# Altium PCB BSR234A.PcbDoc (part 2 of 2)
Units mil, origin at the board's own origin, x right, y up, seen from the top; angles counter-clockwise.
Board outline 3000 x 2500 mil, 4 copper layers (Top Layer, Signal Layer 1, Signal Layer 2, Bottom Layer), stack 61.2 mil thick; 82 components, 24 nets, 148 pads, 419 vias.
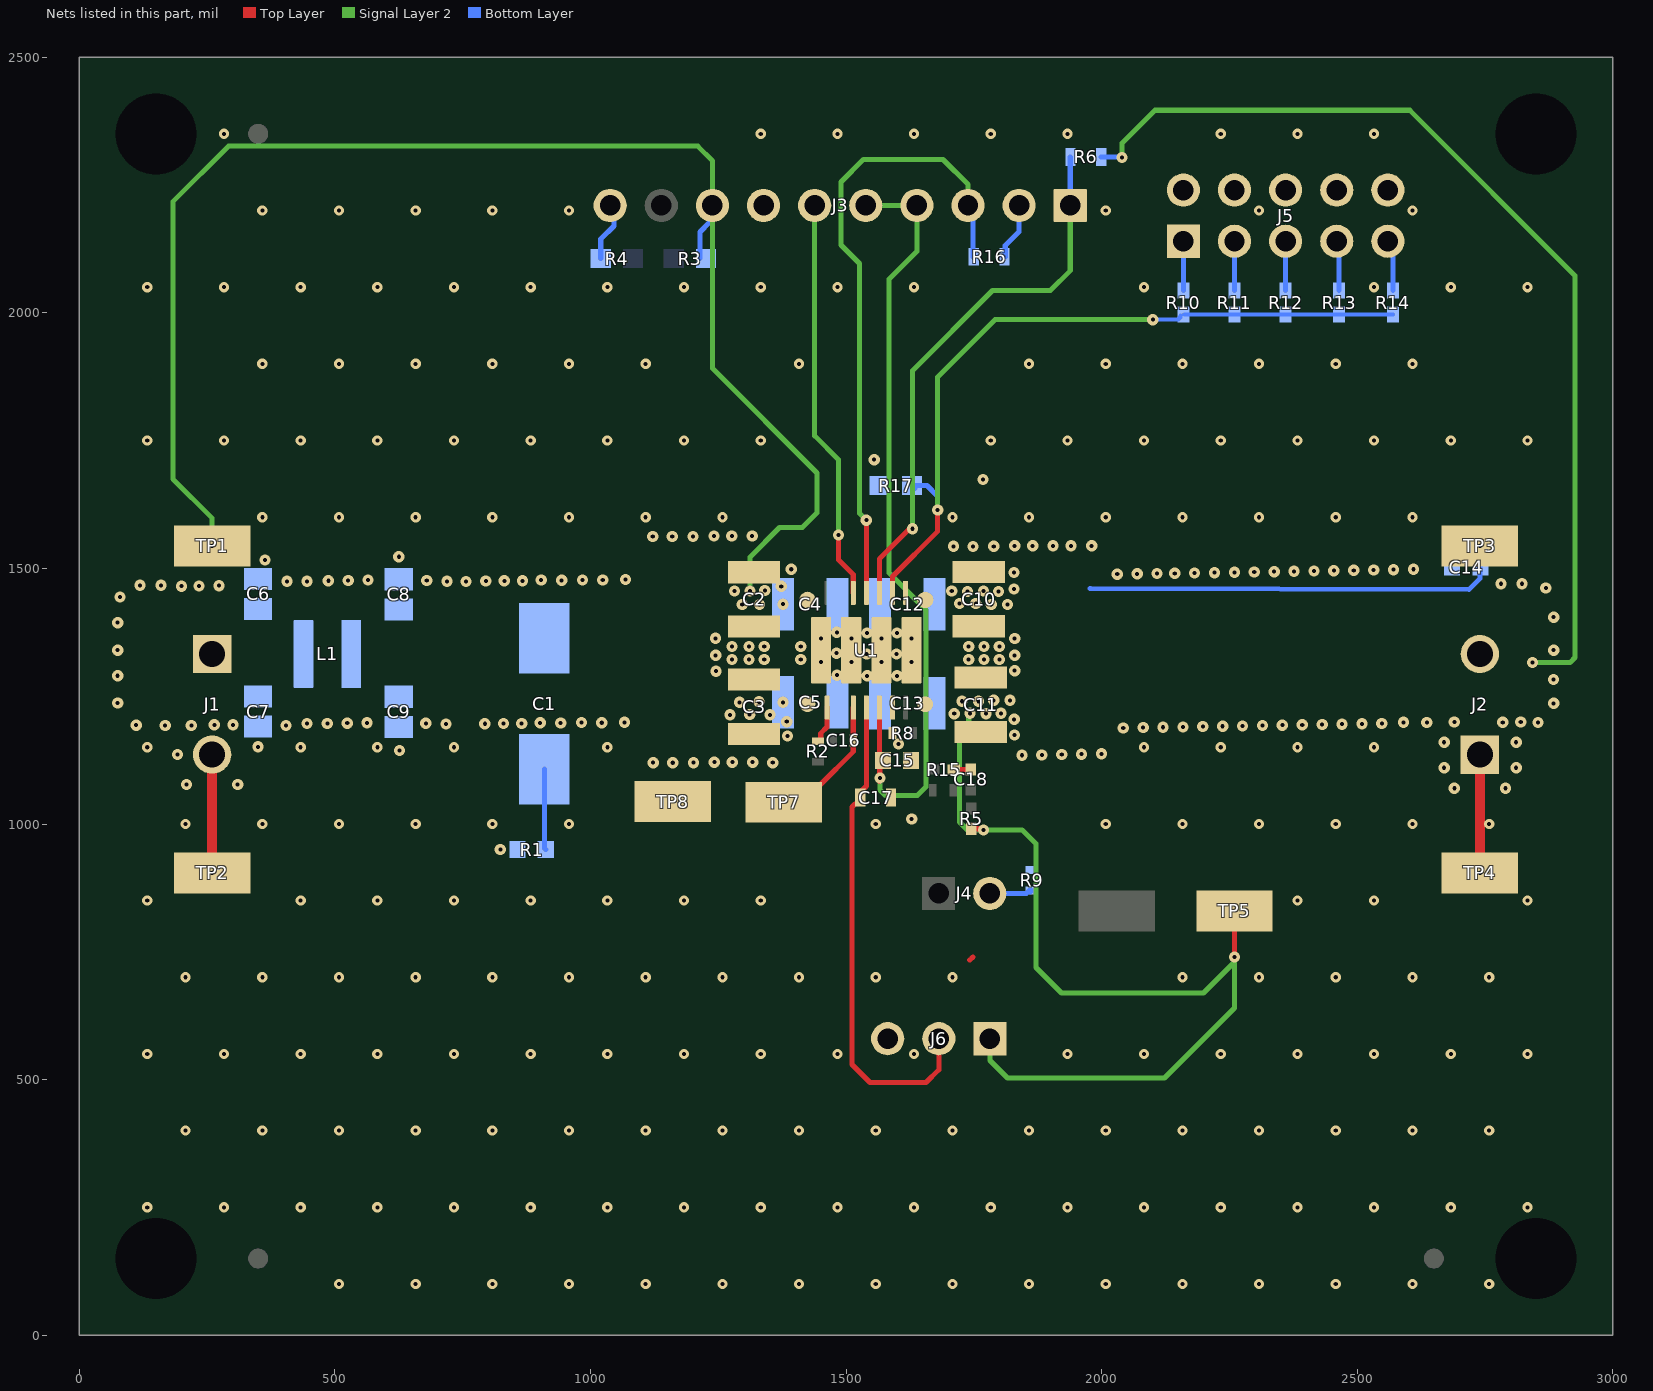
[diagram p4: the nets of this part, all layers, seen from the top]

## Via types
v1: diameter 22, hole 8, Top Layer to Bottom Layer, tented both sides, 213 vias
v2: diameter 20, hole 8, Top Layer to Bottom Layer, tented both sides, 196 vias
v3: diameter 19.68, hole 7.87, Top Layer to Bottom Layer, tented both sides, 8 vias
v4: diameter 22, hole 8, Top Layer to Bottom Layer, 2 vias

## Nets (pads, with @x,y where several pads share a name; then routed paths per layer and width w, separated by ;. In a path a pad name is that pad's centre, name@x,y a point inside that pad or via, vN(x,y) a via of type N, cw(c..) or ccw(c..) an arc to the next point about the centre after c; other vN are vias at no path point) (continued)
GND: C2.1 C3.1 C4.1 C5.1 C6.2 C7.2 C8.2 C9.2 C10.1 C11.1 C12.2 C13.2 C14.2 C15.2 C17.1 J1.2 J2.1 J3.2 J3.7 J3.10 J5.2 J5.4 J5.6 J5.8 J5.10 J6.3 R1.1 R4.1 R8.1 R9.1 R16.1 R17.1 TP2.1 TP4.1 TP8.1 U1.7 U1.11 U1.19 U1.20 U1.21 U1.22 | length 704.4
  Top Layer w10: 1742.12,733.61 1748.5,740
  Top Layer w20: v1(260,904.16) J1.2@260,1135.73 ; v1(2740,904.16) J2.1@2740,1135.73
  Bottom Layer w10: R4.1@1020.33,2106.16 1020.33,2144.25 1046.08,2170 J3.10@1046.08,2216.16 ; R16.1@1811.5,2109.7 1811.5,2131.5 1838.67,2158.67 J3.2@1838.67,2210
  other v1: 823.77,950 1628.43,1010 2690,1070 2790,1070 210,1077.15 310,1077.15 2670.16,1110 2811,1110 1122.77,1120 1161.01,1119.82 1201.6,1120 1356.73,1120 1242.47,1120.99 1277.62,1120.99 1317.4,1120.99 1844.16,1134.56 1883.07,1135.22 192.08,1135.73 1921.98,1135.89 1960.89,1136.55 1999.8,1137.22 626.39,1143.84 349.76,1150.94 1602.69,1156.5 2670.16,1160 2811,1160 2042.35,1187.96 2081.26,1188.62 2120.17,1189.29 2159.09,1189.95 2198,1190.62 2236.91,1191.28 168.19,1192.61 219.37,1192.61 404.65,1192.61 2275.82,1191.95 2314.73,1192.61 111.38,1193.28 2353.64,1193.28 264.24,1193.94 301.06,1193.94 2392.55,1193.94 2431.46,1194.61 717.52,1195.46 2470.37,1195.27 445.36,1196.6 485.35,1196.6 793.49,1196.03 829.74,1196.46 865.46,1196.46 2509.28,1195.94 2548.19,1196.6 524.26,1197.27 677.98,1196.9 941.8,1197.42 563.17,1197.93 901.78,1197.93 982.51,1198.33 1022.13,1198.03 2636.2,1198.33 2853.94,1198.33 1066.84,1198.93 2590.85,1198.93 2690,1199.32 2784.84,1198.93 2820,1199.32 75.22,1236.52 2884.42,1236.11 2884.22,1282.47 75.22,1290 1541.34,1289.82 1599.89,1289.82 1482.38,1291.15 1245.51,1298.92 1830,1300 1277,1322 1310,1322 1340,1322 1411.43,1322 1740,1322 1770,1322 1800,1322 1245.06,1330 1830,1330 1540.47,1332.8 1599.02,1332.8 1481.52,1334.13 75.22,1340 2884.42,1340 1277,1347 1310,1347 1340,1347 1411.43,1347 1740,1347 1770,1347 1800,1347 1830,1362.64 1244.5,1363.27 1541.04,1373.55 1599.59,1373.55 1482.08,1374.88 75.22,1393.9 2884.42,1404.66 80,1443.85 2869.08,1461.81 199.95,1465.26 234.51,1465.56 273.43,1466.22 118.98,1466.88 160,1466.88 2781.41,1470 2822.52,1470 756.52,1474.25 406.47,1474.67 445.36,1474.67 719.44,1474.67 795.41,1475.25 487.27,1475.82 526.18,1476.48 679.91,1476.11 831.66,1475.67 867.39,1475.67 943.72,1476.64 565.09,1477.15 903.7,1477.15 984.43,1477.55 1024.06,1477.24 1068.77,1478.15 2030.69,1488.67 2069.6,1489.34 2108.51,1490 2143.08,1490.3 2181.99,1490.96 2220.9,1491.63 2259.81,1492.29 2298.72,1492.96 2337.63,1493.62 2376.54,1494.29 2415.45,1494.95 2454.36,1495.62 2493.27,1496.28 2532.18,1496.95 2571.09,1497.61 2610,1498.28 363.58,1516.66 625.3,1522.75 1710.27,1543.17 1748.5,1542.99 1789.1,1543.17 1829.97,1544.16 1865.12,1544.16 1904.89,1544.16 1940,1544.16 1980.62,1544.16 1121.87,1562.56 1160.11,1562.39 1200.71,1562.56 1241.58,1563.56 1276.73,1563.56 1316.5,1563.56 1768.07,1673.73 1555.14,1712.79
  other v2: 508.16,100.16 658.16,100.16 808.16,100.16 958.16,100.16 1108.16,100.16 1258.16,100.16 1408.16,100.16 1558.16,100.16 1708.16,100.16 1858.16,100.16 2008.16,100.16 2158.16,100.16 2308.16,100.16 2458.16,100.16 2608.16,100.16 2758.16,100.16 133.16,250.16 283.16,250.16 433.16,250.16 583.16,250.16 733.16,250.16 883.16,250.16 1033.16,250.16 1183.16,250.16 1333.16,250.16 1483.16,250.16 1633.16,250.16 1783.16,250.16 1933.16,250.16 2083.16,250.16 2233.16,250.16 2383.16,250.16 2533.16,250.16 2683.16,250.16 2833.16,250.16 208.16,400.16 358.16,400.16 508.16,400.16 658.16,400.16 808.16,400.16 958.16,400.16 1108.16,400.16 1258.16,400.16 1408.16,400.16 1558.16,400.16 1708.16,400.16 1858.16,400.16 2008.16,400.16 2158.16,400.16 2308.16,400.16 2458.16,400.16 2608.16,400.16 2758.16,400.16 133.16,550.16 283.16,550.16 433.16,550.16 583.16,550.16 733.16,550.16 883.16,550.16 1033.16,550.16 1183.16,550.16 1333.16,550.16 1483.16,550.16 1633.16,550.16 1933.16,550.16 2083.16,550.16 2233.16,550.16 2383.16,550.16 2533.16,550.16 2683.16,550.16 2833.16,550.16 208.16,700.16 358.16,700.16 508.16,700.16 658.16,700.16 808.16,700.16 958.16,700.16 1108.16,700.16 1258.16,700.16 1408.16,700.16 1558.16,700.16 1708.16,700.16 2158.16,700.16 2308.16,700.16 2458.16,700.16 2608.16,700.16 2758.16,700.16 133.16,850.16 433.16,850.16 583.16,850.16 733.16,850.16 883.16,850.16 1033.16,850.16 1183.16,850.16 1333.16,850.16 2383.16,850.16 2533.16,850.16 2833.16,850.16 208.16,1000.16 358.16,1000.16 508.16,1000.16 658.16,1000.16 808.16,1000.16 958.16,1000.16 1558.16,1000.16 2008.16,1000.16 2158.16,1000.16 2308.16,1000.16 2458.16,1000.16 2608.16,1000.16 2758.16,1000.16 133.16,1150.16 433.16,1150.16 583.16,1150.16 733.16,1150.16 1033.16,1150.16 2083.16,1150.16 2233.16,1150.16 2383.16,1150.16 2533.16,1150.16 358.16,1600.16 508.16,1600.16 658.16,1600.16 808.16,1600.16 958.16,1600.16 1108.16,1600.16 1258.16,1600.16 1708.16,1600.16 1858.16,1600.16 2008.16,1600.16 2158.16,1600.16 2308.16,1600.16 2458.16,1600.16 2608.16,1600.16 133.16,1750.16 283.16,1750.16 433.16,1750.16 583.16,1750.16 733.16,1750.16 883.16,1750.16 1033.16,1750.16 1183.16,1750.16 1333.16,1750.16 1783.16,1750.16 1933.16,1750.16 2083.16,1750.16 2233.16,1750.16 2383.16,1750.16 2533.16,1750.16 2683.16,1750.16 2833.16,1750.16 358.16,1900.16 508.16,1900.16 658.16,1900.16 808.16,1900.16 958.16,1900.16 1108.16,1900.16 1408.16,1900.16 1858.16,1900.16 2008.16,1900.16 2158.16,1900.16 2308.16,1900.16 2458.16,1900.16 2608.16,1900.16 133.16,2050.16 283.16,2050.16 433.16,2050.16 583.16,2050.16 733.16,2050.16 883.16,2050.16 1033.16,2050.16 1183.16,2050.16 1333.16,2050.16 1483.16,2050.16 1633.16,2050.16 2083.16,2050.16 2533.16,2050.16 2683.16,2050.16 2833.16,2050.16 358.16,2200.16 508.16,2200.16 658.16,2200.16 808.16,2200.16 958.16,2200.16 2008.16,2200.16 2308.16,2200.16 2608.16,2200.16 283.16,2350.16 1333.16,2350.16 1483.16,2350.16 1633.16,2350.16 1783.16,2350.16 1933.16,2350.16 2233.16,2350.16 2383.16,2350.16 2533.16,2350.16
  other v3: 1451.27,1317.36 1510.32,1317.36 1569.38,1317.36 1628.43,1317.36 1451.27,1362.64 1510.32,1362.64 1569.38,1362.64 1628.43,1362.64
MODE: J3.6 U1.15 | length 799.1
  Top Layer w10: v1(1485.32,1565.57) 1485.32,1532.26 1485.51,1532.08 1485.51,1516.97 1514.26,1488.22 U1.15@1514.26,1452.2
  Signal Layer 2 w10: J3.6@1438.67,2220 J3.6@1438.67,2210 1438.67,1759.45 1485.32,1712.79 v1(1485.32,1565.57)
NetC1_2: C1.2 R1.2 | length 158.1
  Bottom Layer w10: C1.2@910,1107.05 910,952.56 R1.2@912.56,950
NetC18_2: C18.2 R15.2 | length 37
  Top Layer w10: R15.2@1710.76,1106.38 C18.2@1747.8,1106.38
NetJ4_2: J4.2 R9.2 | length 87.8
  Bottom Layer w10: J4.2@1781.23,864.16 1852.74,864.16 1858.58,870 R9.2@1863.08,870 R9.2@1860.57,867.5
NetJ5_1: J5.1 R10.1 | length 96.4
  Bottom Layer w10: R10.1@2160,2043.62 J5.1@2160,2140
NetJ5_3: J5.3 R11.1 | length 96.4
  Bottom Layer w10: R11.1@2260,2043.62 J5.3@2260,2140
NetJ5_5: J5.5 R12.1 | length 96.4
  Bottom Layer w10: R12.1@2360,2043.62 J5.5@2360,2140
NetJ5_7: J5.7 R13.1 | length 98.3
  Bottom Layer w10: J5.7@2460,2140 2464.6,2135.4 R13.1@2464.6,2043.62
NetJ5_9: J5.9 R14.1 | length 100.5
  Bottom Layer w10: J5.9@2560,2140 2570,2130 R14.1@2570,2043.62
RBOOT: R2.1 U1.2 | length 72.6
  Top Layer w10: R2.1@1449,1161 1450.52,1162.52 1450.52,1177.35 1463.08,1189.91 U1.2@1463.08,1227.8
RESET: J3.1 R6.1 U1.13 | length 1077.2
  Top Layer w10: U1.13@1565.44,1452.2 1565.44,1518.74 1565.59,1518.74 1624.37,1577.52 v1(1630,1577.52)
  Signal Layer 2 w10: v1(1630,1577.52) 1630,1886.81 1786.81,2043.62 1899.79,2043.62 1938.67,2082.5 J3.1@1938.67,2210
  Bottom Layer w10: J3.1@1938.67,2210 1938.67,2304.45 R6.1@1939.2,2304.98
RT: R10.2 R11.2 R12.2 R13.2 R14.2 R17.2 U1.12 | length 1492.9
  Top Layer w10: U1.12@1591.03,1452.2 1591.03,1484.18 1679.36,1572.51 v1(1679.36,1614.15)
  Signal Layer 2 w10: v1(1679.36,1614.15) 1679.36,1874.63 1791.39,1986.66 v1(2100.32,1986.66)
  Bottom Layer w8: v1(2100.32,1986.66) 2148.63,1986.66 2154.47,1992.5 R10.2@2154.47,1994.22 ; R10.2@2150.54,1986.66 R10.2@2154.47,1990.6 ; R10.2@2161.68,1996.38 R14.2@2570,1996.38
  Bottom Layer w10: R17.2@1634.61,1656.14 R17.2@1628.75,1662 1658.28,1662 1679.36,1640.92 v1(1679.36,1614.15)
SPSP: J3.3 R16.2 U1.14 | length 1257.2
  Top Layer w10: U1.14@1539.85,1452.2 v1(1539.85,1594.37)
  Signal Layer 2 w10: v1(1539.85,1594.37) 1526.3,1607.91 1526.3,2096.39 1490,2132.69 1490,2256.03 1533.97,2300 1690,2300 1738.67,2251.33 J3.3@1738.67,2210
  Bottom Layer w10: J3.3@1738.67,2210 1748.5,2200.16 R16.2@1748.5,2109.7
SW: C16.1 TP7.1 U1.4 | length 196.3
  Top Layer w10: TP7.1@1330,1040 TP7.1@1347.6,1040 ; TP7.1@1448.98,1076.25 1514.26,1141.53 1514.26,1163.53 U1.4@1514.26,1227.8 U1.4@1514.37,1227.68
VCC: C15.1 J3.4 J3.5 U1.6 | length 1602.9
  Top Layer w10: v1@1565.37,1083.02 1565.37,1090.15 1565.39,1124.59 U1.6@1565.44,1227.8 ; v1(1566.68,1090.15) C15.1@1566.68,1133.17
  Signal Layer 2 w10: J3.5@1538.67,2210 J3.4@1638.67,2210 1638.67,2120.24 1584.14,2065.71 1584.14,1491.28 1656.62,1418.79 1656.62,1072.78 1639.44,1055.59 1577.49,1055.59 1566.68,1066.41 v1(1566.68,1090.15)
VIN: C1.1 C2.2 C3.2 C4.2 C5.2 C8.1 C9.1 J3.8 L1.1 R3.1 TP1.1 U1.1 U1.18 | length 2945.5
  Signal Layer 2 w10: v4(260,1544.16) 260,1598.31 183.19,1675.13 183.19,2217.22 292,2326.03 1210,2326.03 1238.67,2297.36 1238.67,1891.33 1443.22,1686.78 1443.22,1608.87 1414.35,1580 1370,1580 1311.96,1521.96 v1(1311.96,1455.73)
  Bottom Layer w10: R3.1@1214.13,2106.16 1214.13,2158.3 1233.47,2177.64 1233.47,2207.79 J3.8@1241.83,2216.16
  other v1: 1385.67,1172.35 1384.03,1200.15 1272.91,1213.57 1351.26,1213.57 1311.53,1213.96 1291.7,1237.97 1376.85,1238 1330,1239 1297.04,1429.63 1330.64,1429.63 1376.85,1430 1282.11,1455.73 1341.18,1456.81 1373.31,1465 1392.96,1498.28
VIN_EMI: C6.1 C7.1 J1.1 L1.2
VLDOIN: C17.2 J6.2 U1.5 | length 969.2
  Top Layer w10: U1.5@1539.85,1227.8 1539.85,1074.43 1526.3,1060.89 1526.3,1042.64 1522.93,1039.26 1517.41,1039.26 1511.55,1033.4 1511.55,529.56 1547.02,494.08 1656.62,494.08 1681.57,519.03 J6.2@1681.57,580
VOUT: C10.2 C11.2 C12.1 C13.1 C14.1 J2.2 J6.1 R5.2 R6.2 TP3.1 TP5.1 U1.9 U1.10 | length 4655.1
  Top Layer w10: R5.2@1747.06,990.77 1766.57,990.77 v1(1769,988.35) ; v1(2260,740) TP5.1@2260,830
  Signal Layer 2 w10: v1(1742.45,1216.52) 1740.15,1214.22 1740.15,1201.05 1722.12,1183.02 1722.12,1004.12 1737.89,988.35 v1(1769,988.35) 1844.61,988.35 1871.52,961.43 1871.52,719.2 1921.45,669.27 2199.27,669.27 v1@2260,730 ; J6.1@1781.57,580 1781.57,537.28 1815.84,503 2123,503 2260,640 v1@2260,730 ; v1(2040,2303.82) 2040,2331.81 2104.38,2396.18 2602.78,2396.18 2926.29,2072.66 2926.29,1325.84 2916.58,1316.13 v1(2842.72,1316.13) ; v1(2260,740) v1@2260,730
  Bottom Layer w10: 1977.91,1460.43 2719.06,1459.06 2740,1480 v4(2740,1544.16) ; R6.2@1999.2,2304.98 2038.84,2304.98 v1(2040,2303.82)
  other v1: 1829.58,1174.15 1829.02,1204.8 1711.81,1215.85 1773.96,1215.81 1803.25,1216.52 1727.08,1240.18 1758.96,1240.18 1788.87,1241.95 1820.75,1241.95 1783.91,1429.63 1815.79,1429.63 1722.12,1431.4 1754,1431.4 1737.49,1455.06 1798.29,1455.06 1706.85,1455.73 1769,1455.77 1828.59,1459.69 1828.59,1492.17
pads on no net: FID1.1 FID2.1 FID3.1 FID4.1 FID5.1 FID6.1 LBL1.0 MH1.1 MH2.1 MH3.1 MH4.1 SH-J1.0 SH-J2.0 SH-J3.0 SH-J4.0 SH-J5.0 SH-J6.0 U1.16

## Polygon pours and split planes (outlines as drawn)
GND on Top Layer "TOP_LAYER_GND_P1027" (solid, remove dead copper, pour order 1027): 0,2500 2990,2500 2990,10 0,10
VIN on Top Layer "TOP_LAYER_VIN_P984" (solid, remove dead copper, pour order 984): 1267.01,1522 1373.31,1522 1373.31,1454 1267.01,1454
VIN on Top Layer "TOP_LAYER_VIN_P983" (solid, remove dead copper, pour order 983): 1373.31,1147.11 1267.01,1147.11 1267.01,1214.55 1373.31,1214.55
VIN on Top Layer "TOP_LAYER_VIN_P1008" (solid, remove dead copper, pour order 1008): 1249.76,1259.29 1417.59,1259.29 1442.41,1259.29 1442.41,1205.23 1373.31,1147.11 1249.76,1147.11
VOUT on Top Layer "TOP_LAYER_VOUT_P1010" (solid, remove dead copper, pour order 1010): 1637.87,1258.71 1637.29,1258.14 1637.29,1205.75 1693.99,1149.06 1857.36,1149.06 1857.36,1259.29 1672.15,1259.29 1639.26,1259.29
VOUT on Top Layer "TOP_LAYER_VOUT_P1014" (solid, remove dead copper, pour order 1014): 1637.59,1474.97 1681.36,1518.74 1837.92,1518.74 1844.71,1511.95 1844.71,1421.56 1672.42,1421.56 1637.29,1421.56 1637.29,1474.05
VIN on Top Layer "TOP_LAYER_VIN_P1004" (solid, remove dead copper, pour order 1004): 1394.27,1522 1442.41,1473.86 1441.56,1473 1441.56,1421.01 1409.24,1421.01 1267.01,1421.01 1267.01,1522
VIN on Bottom Layer "BOTTOM_LAYER_VIN_P1029" (solid, pour order 1029): 513.26,1444.32 511.47,1444.12 535.07,1444.12 535.07,1228.03 538.93,1224.16 511.47,1224.16
VIN on Bottom Layer "BOTTOM_LAYER_VIN_P1001" (solid, remove dead copper, pour order 1001): 538.31,1444.31 1436.98,1444.32 1436.98,1408.8 cw(c1408.18,1408.8) 1408.18,1380.01 1281.13,1380.01 cw(c1281.13,1389.72) 1271.42,1389.72 1271.42,1402.98 1186.33,1402.98 1186.33,1268.16 1271.42,1268.16 1271.42,1278.75 cw(c1281.07,1278.75) 1281.07,1288.4 1404.77,1288.4 cw(c1404.77,1256.2) 1436.98,1256.2 1436.98,1224.16 539.31,1224.16 cw(c539.31,1239.07) 524.39,1239.07 524.39,1430.32 cw(c538.31,1430.4)
VOUT on Bottom Layer "BOTTOM_LAYER_VOUT_P1002" (solid, remove dead copper, pour order 1002): 1612.43,1444.16 2837.99,1444.16 cw(c2837.99,1422.49) 2859.66,1422.49 2859.66,1243.01 cw(c2840.81,1243) 2840.81,1224.16 1612.43,1224.16 1612.43,1257.61 cw(c1643.74,1257.61) 1643.74,1288.92 1767.67,1288.92 cw(c1767.67,1277.69) 1778.9,1277.69 1778.9,1268.16 1860.55,1268.16 1860.55,1402.76 1778.9,1402.76 1778.9,1390.63 cw(c1767.9,1390.63) 1767.9,1379.63 1640.19,1379.63 cw(c1640.19,1407.39) 1612.43,1407.39
VIN_EMI on Bottom Layer "BOTTOM_LAYER_VIN_EMI_P1000" (solid, remove dead copper, pour order 1000): 129.28,1444.76 443.22,1444.76 cw(c443.22,1430.52) 457.46,1430.52 457.46,1242.08 cw(c439.98,1242.08) 439.98,1224.6 127.96,1224.6 cw(c127.96,1242.7) 109.87,1242.7 109.87,1425.34 cw(c129.28,1425.34)
VOUT on Bottom Layer "BOTTOM_LAYER_VOUT_P999" (solid, remove dead copper, pour order 999): 2000.26,1434 2000.26,1484.36 ccw(c1980.62,1484.36) 1980.62,1504 1638.88,1504 ccw(c1638.88,1477.55) 1612.43,1477.55 1612.43,1434
VOUT on Bottom Layer "BOTTOM_LAYER_VOUT_P998" (solid, remove dead copper, pour order 998): 2000.26,1196.6 2000.26,1235 1612.43,1235 1612.43,1190.45 ccw(c1631.66,1190.45) 1631.66,1171.22 1974.88,1171.22 ccw(c1974.88,1196.6)
VIN on Bottom Layer "BOTTOM_LAYER_VIN_P997" (solid, remove dead copper, pour order 997): 1437.17,1429.89 1437.17,1511.49 ccw(c1420.39,1511.49) 1420.39,1528.28 1131.67,1528.28 ccw(c1131.6,1516.67) 1120,1516.67 1120,1429.89
VIN on Bottom Layer "BOTTOM_LAYER_VIN_P996" (solid, remove dead copper, pour order 996): 1437.17,1168.37 1437.17,1231.9 1121.82,1231.9 1121.82,1159.64 ccw(c1130.95,1159.64) 1130.95,1150.51 1419.37,1150.51 ccw(c1419.31,1168.37)
GND on Bottom Layer "BOTTOM_LAYER_GND_P1020" (solid, remove dead copper, pour order 1020): 0,2510 2990,2510 2990,20 0,20
GND on Signal Layer 1 "SIGNAL_LAYER_1_GND_P1016" (solid, remove dead copper, pour order 1016): 0,2500 2990,2500 2990,10 0,10
GND on Signal Layer 2 "SIGNAL_LAYER_2_GND_P1026" (solid, remove dead copper, pour order 1026): 0,2510 2990,2510 2990,20 0,20

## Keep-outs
Keep-Out Layer:
  text ".Layer_Name" at 577.16,-874.34 h60

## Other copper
Top Layer:
  text ".Layer_Name" at 577.16,-874.34 h60
Signal Layer 1:
  text ".Layer_Name" at 577.16,-874.34 h60
Signal Layer 2:
  text ".Layer_Name" at 577.16,-865.84 h60
Bottom Layer:
  pour cut-out: 497.8,1454.23 465.16,1454.06 465.16,1213.96 497.61,1213.96
  pour cut-out: 432.92,1454.32 433.12,1454.51 537.07,1454.51 537.07,1444.32 536.87,1444.12 432.92,1444.12
  pour cut-out: 539.31,1213.96 429.87,1213.96 429.68,1213.77 429.68,1223.97 539.12,1223.97 539.31,1224.16
  pour cut-out: 1410.93,1380.01 1271.42,1380.01 1271.42,1368.82 1411.11,1368.82
  pour cut-out: 1410.98,1299.59 1271.42,1299.59 1271.42,1288.4 1411.16,1288.4
  pour cut-out: 1778.54,1300.1 1638.82,1300.1 1638.82,1288.92 1778.72,1288.92
  pour cut-out: 1779.07,1379.63 1639.27,1379.63 1639.27,1368.45 1779.25,1368.45
  text ".Layer_Name" at 577.16,-874.34 h60

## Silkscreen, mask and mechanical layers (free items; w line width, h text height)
Top Overlay:
  lines w8: 988.91,2266.91 988.91,2411.48 1300,2411.48 ; 1300.66,2411.48 1611.75,2411.48 ; 1310,2266.91 1310,2411.48 ; 1607.38,2266.91 1607.38,2411.48 ; 1610.94,2411.48 1888.67,2411.48 1888.67,2266.91
  lines w10: 1830,512.22 1830.52,512.22
  text "PG" at 1938.67,2297.36 h25 r46.96
  text "EN" at 1150,2294.32 h25 r54.7
  text "GND" at 1350,2294.32 h40 r54.64
  text "MODE" at 1431.69,2294.32 h40 r54.64
  text "GND" at 1817.05,2290 h25 r52.62
  text "VIN" at 1250,2288.68 h25 r54.7
  text "VCC" at 1644.13,2286.41 h25 r45.33
  text "SPSP" at 1722.95,2285.29 h25 r49.61
  text "VCC" at 1530.27,2284.04 h25 r51.75
  text "GND" at 1038.27,2266.91 h25 r54.7
  text "EN  / SELECT" at 1030,2020 h30
  text "MODE / SELECT" at 1340,2020 h30
  text "SPSP / SELECT" at 1620,2020 h30
  text "TPSM63610EVM" at 118,2018 h60
  text "1 MHz" at 2371.09,1949 h25 r90
  text "'.PRJ_Number''.PCB_Rev'" at 129,1927 h60
  text "1.4 MHz" at 2480,1922 h25 r90
  text "2.2 MHz" at 2585.29,1922 h25 r90
  text "400 kHz" at 2173,1909 h25 r90
  text "700 kHz" at 2271.09,1909 h25 r90
  text "V   = 6V to 36V" at 124.52,1865.37 h60
  text "IN" at 161.57,1864.7 h40
  text "V      = 5V/3.3V" at 124.52,1810.37 h60
  text "OUT" at 157.58,1810.15 h40
  text "FSW  / SELECT" at 2248.91,1759.45 h30
  text "I      = 0A to 8A (10A peak)" at 133.52,1755.37 h60
  text "OUT" at 145.99,1755.15 h40
  text "S+" at 2780,1630 h30
  text "VOUT" at 2660.62,1629.06 h30
  text "VIN" at 210,1625 h30
  text "S+" at 281.19,1625 h30
  text "VOUT+" at 2415.45,1323.27 h30
  text "VIN+" at 465.16,1314.32 h30
  text "VIN-" at 465.16,1094.32 h30
  text "VOUT-" at 2415.45,1090.15 h30
  text "VOUT" at 2658,799 h30
  text "S-" at 2773.81,799 h30
  text "VIN" at 210,790 h30
  text "S-" at 281.06,790 h30
  text "OPEN  = 3.3V / SHORT = 5V" at 1538,690 h30
  text "GND" at 1466.03,427 h25
  text "VOUT" at 1641.23,420 h25
  text "VLDOIN / SELECT" at 1553.35,327 h30
  text ".Layer_Name" at 577.16,-874.34 h35
Bottom Overlay:
  text ".Layer_Name" at 577.16,-874.34 h60
Top Paste:
  text ".Layer_Name" at 577.16,-874.34 h60
Bottom Paste:
  text ".Layer_Name" at 577.16,-874.34 h60
Top Solder:
  text ".Layer_Name" at 577.16,-874.34 h60
  text ".Layer_Name" at 577.16,-874.34 h60
Bottom Solder:
  text ".Layer_Name" at 577.16,-874.34 h60
Drill Guide:
  text ".Layer_Name" at 577.16,-874.34 h60
M1 Board Outline:
  lines w47.24: 0,0 0,2500 ; 0,0 3000,0 ; 0,0 3000,0 ; 0,0 0,2500 ; 0,2500 3000,2500 ; 0,2500 3000,2500 ; 3000,0 3000,2500 ; 3000,0 3000,2500
  text ".Layer_Name" at 577.16,-874.34 h60
M2 Board Dimensions:
  rectangle: 125.16,-415.84 500.16,-290.84
  rectangle: 0.16,-290.84 125.16,-165.84
  lines w7: 0.16,-290.84 1000.16,-290.84 ; 125.16,-415.84 125.16,-165.84 ; 250.16,-415.84 250.16,-165.84 ; 500.16,-415.84 500.16,-165.84 ; 750.16,-415.84 750.16,-165.84 ; 0.16,-415.84 0.16,-165.84 1000.16,-165.84 1000.16,-415.84 0.16,-415.84
  text ".Layer_Name" at 577.16,-874.34 h60
M3 3D STEP Top:
  text ".Layer_Name" at 577.16,-874.34 h60
M4 3D STEP Bottom:
  text ".Layer_Name" at 577.16,-874.34 h60
M5 Assembly Top:
  lines w10: -291.84,-946.01 6308.16,-946.01 ; -291.84,-742.68 6310.16,-742.68 ; -291.84,-539.34 -291.84,-1149.34 3713.16,-1149.34 6310.16,-1149.34 6310.16,-539.34 -291.34,-539.34 -291.34,-1149.34 1284.16,-1149.34 ; 2173.16,-1149.34 2173.16,-539.34 ; 3440.16,-742.68 3440.16,-539.34 ; 4280.16,-742.68 4280.16,-539.34 ; 4902.16,-1155.84 4902.16,-953.01
  text "COMPONENTS MARKED 'DNP' SHOULD NOT BE POPULATED." at 1153.66,-334.34 h60
  text "ASSEMBLY VARIANT:" at 1153.16,-449.84 h60
  text ".VariantName" at 2189.16,-449.84 h60
  text "PCB VIEWED FROM TOP SIDE" at -228.34,-671.51 h60
  text "BOARD #:" at 2248.16,-671.51 h60
  text ".PRJ_Number" at 2793.66,-671.51 h60
  text "REV:" at 3638.16,-671.51 h60
  text ".PCB_Rev" at 3929.66,-671.51 h60
  text "SVN REV:" at 4476.16,-671.51 h60
  text ".VersionControl_RevNumber" at 4982.16,-671.51 h60
  text "TID #:" at 2248.16,-874.84 h60
  text ".TID" at 2793.66,-874.84 h60
  text "PLOT NAME =" at -228.34,-1080.18 h60
  text ".plot_File_Name" at 577.16,-1080.18 h60
  text "GENERATED    :" at 2250.16,-1080.18 h60
  text ".Print_Date" at 3119.66,-1080.18 h60
  text ".Print_Time" at 3848.66,-1080.18 h60
  text "TEXAS INSTRUMENTS" at 5113.16,-1080.18 h60
M6 Assembly Bottom:
  lines w10: -292.34,-743.18 6309.66,-743.18 ; -290.34,-946.51 6309.66,-946.51 ; 1115.66,-1156.34 1115.66,-953.51 ; 1737.66,-743.18 1737.66,-539.84 ; 2577.66,-743.18 2577.66,-539.84 ; 3844.66,-1149.84 3844.66,-539.84 ; 4733.66,-1149.84 6309.16,-1149.84 6309.16,-539.84 -292.34,-539.84 -292.34,-1149.84 2304.66,-1149.84 6309.66,-1149.84 6309.66,-539.84
  text "COMPONENTS MARKED 'DNP' SHOULD NOT BE POPULATED." at 6102.16,-333.84 h60
  text ".VariantName" at 5058.16,-449.84 h60
  text "ASSEMBLY VARIANT:" at 6097.16,-449.84 h60
  text ".VersionControl_RevNumber" at 1035.66,-672.01 h60
  text "SVN REV:" at 1541.66,-672.01 h60
  text ".PCB_Rev" at 2088.16,-672.01 h60
  text "REV:" at 2379.66,-672.01 h60
  text ".PRJ_Number" at 3224.16,-672.01 h60
  text "BOARD #:" at 3769.66,-672.01 h60
  text "PCB VIEWED FROM BOTTOM SIDE" at 6246.16,-672.01 h60
  text ".TID" at 3224.16,-875.34 h60
  text "TID #:" at 3769.66,-875.34 h60
  text "TEXAS INSTRUMENTS" at 904.66,-1080.68 h60
  text ".Print_Time" at 2169.16,-1080.68 h60
  text ".Print_Date" at 2898.16,-1080.68 h60
  text "GENERATED    :" at 3767.66,-1080.68 h60
  text ".plot_File_Name" at 5440.66,-1080.68 h60
  text "PLOT NAME =" at 6246.16,-1080.68 h60
M9 Title Sheet:
  drawing of 57 lines, arcs and shapes, not listed
  text "1" at 739.99,8020.66 h70
  text "2" at 3235.66,8020.66 h70
  text "3" at 5725,8020.66 h70
  text "4" at 8231.67,8020.66 h70
  text "5" at 10730.66,8020.66 h70
  text "6" at 13235.66,8020.66 h70
  text "A" at -416.34,6877.66 h70
  text "A" at 14383.66,6877.66 h70
  text "B" at -416.34,4497.66 h70
  text "B" at 14383.66,4497.66 h70
  text "C" at -416.34,2122.66 h70
  text "C" at 14383.66,2122.66 h70
  text "PROJECT TITLE:" at 11343.66,261.66 h45
  text ".PRJ_Title" at 11393.66,128.33 h70
  text "DESIGNED FOR:" at 11343.66,-39.34 h45
  text ".PRJ_Customer" at 11393.66,-179.34 h70
  text "D" at -416.34,-247.34 h70
  text "D" at 14383.66,-247.34 h70
  text "FILE NAME:" at 11343.66,-339.34 h45
  text ".PCB_File_Name_No_Path" at 11393.66,-459.34 h70
  text "Texas Instruments (TI) and/or its licensors do not warrant the accuracy or completeness of this specification" at 6374.16,-621.18 h45
  text "ENGINEER:" at 11343.66,-629.34 h45
  text "LAYOUT BY:" at 12848.66,-629.34 h45
  text "or any information contained therein. TI and/or its licensors do not warrant that this design will meet" at 6329.17,-733.85 h45
  text ".PRJ_Engineer" at 11393.66,-784.33 h70
  text ".PCB_Layout" at 12899.16,-784.33 h70
  text "the specifications, will be suitable for your application or fit for any particular purpose, or will operate in" at 6329.17,-846.51 h45
  text ".Layer_Name" at 577.16,-874.34 h60
  text "ALTIUM DESIGNER VERSION:" at 12848.66,-939.34 h45
  text "an implementation. TI and/or its licensors do not warrant that the design is production worthy. You should" at 6329.17,-959.18 h45
  text "completely validate and test your design implementation to confirm the system functionality for your application." at 6374.16,-1071.84 h45
  text ".print_Scale" at 11393.66,-1072.67 h70
  text ".Application_BuildNumber" at 12899.16,-1072.67 h70
  text "1" at 739.99,-1279.34 h70
  text "2" at 3235.66,-1279.34 h70
  text "3" at 5725,-1279.34 h70
  text "4" at 8231.67,-1279.34 h70
  text "5" at 10730.66,-1279.34 h70
  text "6" at 13235.66,-1279.34 h70
M10 Fab Notes:
  drawing of 189 lines, arcs and shapes, not listed
  text "DESIGN INFORMATION" at 12382.18,6340.33 h60
  text "MIN. TRACK WIDTH:" at 11737.62,6208.21 h60
  text "8" at 12833.86,6208.21 h60
  text "MIL" at 12988.62,6208.21 h60
  text "MIN. CLEARANCE:" at 11737.62,6084.08 h60
  text "0.2" at 12773.86,6084.08 h60
  text "mm" at 12988.62,6084.08 h60
  text "MIN. VIA PAD SIZE:" at 11737.62,5959.95 h60
  text "19" at 12803.87,5959.96 h60
  text "MIL" at 12988.62,5959.95 h60
  text "0.05mm (2MIL)" at 12432.62,5830.05 h60
  text "MINIMUM ANNULAR RING" at 11408.39,5821.83 h60
  text "EXTERNAL" at 13140.62,5821.83 h60
  text "PER" at 11608.39,5711.71 h60
  text "IPC-D-275 CLASS 2 LEVEL C" at 11828.39,5711.7 h60
  text "MIL, HOLES" at 13316.62,5611.23 h60
  text "+/-" at 12924.16,5602.64 h60
  text "+/-" at 13778.16,5602.64 h60
  text "REGISTRATION TOLERANCES:" at 11408.39,5601.58 h60
  text "METAL" at 12608.16,5601.58 h60
  text "5" at 13184.36,5601.58 h60
  text "3" at 14017.36,5601.58 h60
  text "MIL" at 14133.62,5601.58 h60
  text "HOLE SIZE TOLERANCE (UNLESS OTHERWISE SPECIFIED):" at 11408.39,5503.26 h60
  text "+/-" at 13778.16,5500.39 h60
  text "3" at 14017.36,5499.33 h60
  text "MIL" at 14133.62,5499.32 h60
  text "MATERIAL:" at 11333.62,5361.68 h60
  text "FR-4 High Tg" at 12320.06,5233.15 h60
  text "X" at 12175.62,5225.16 h60
  text "FR-408" at 11754.62,5220.65 h60
  text "OTHER" at 13242.62,5220.65 h60
  text "62 MIL (1.6mm) +/-10%" at 12074.72,5077.62 h60
  text "X" at 11954.62,5075.16 h60
  text "THICKNESS:" at 11408.39,5069.39 h60
  text "OTHER" at 13359.62,5069.39 h60
  text "TOLERANCE:" at 11408.39,4931.08 h60
  text "X" at 12256.62,4931.08 h60
  text "ANSI IPC-6012 TYPE 3 CLASS 2" at 12434.63,4931.08 h60
  text "OTHER +/-" at 12434.62,4786.89 h60
  text "BOW & TWIST:" at 11408.39,4641.7 h60
  text "X" at 12256.62,4641.7 h60
  text "ANSI IPC-6012 TYPE 3 CLASS 2" at 12434.63,4641.7 h60
  text "OTHER +/-" at 12434.62,4495.01 h60
  text "DRILLING:" at 11333.62,4364.39 h60
  text "NC_DRILL FILES" at 13094.62,4259.2 h60
  text "REFERENCE:" at 11408.39,4255.26 h60
  text "X" at 12065.62,4255.16 h60
  text "AS SHOWN" at 12243.62,4255.26 h60
  text "X" at 12966.62,4255.26 h60
  text "OTHER" at 13392.62,4113.01 h60
  text "PTH COPPER THICKNESS:" at 11408.06,4109.48 h60
  text "X" at 12547.3,4109.48 h60
  text "20-30 um" at 12675.29,4109.48 h60
  text "BOARD FINISH:" at 11333.62,3961.88 h60
  text "SILKSCREEN:" at 11488.84,3851.76 h60
  text "X" at 12446.62,3851.76 h60
  text "TOP" at 12563.62,3851.76 h60
  text "X" at 12956.62,3851.76 h60
  text "BOTTOM" at 13074.62,3851.76 h60
  text "SILKSCREEN COLOR:" at 11488.84,3696.57 h60
  text "X" at 12445.62,3696.57 h60
  text "WHITE" at 12563.62,3696.57 h60
  text "OTHER" at 13074.62,3696.57 h60
  text "X" at 12576.62,3553.12 h60
  text "GREEN" at 12694.62,3553.12 h60
  text "OTHER" at 13312.62,3553.12 h60
  text "SOLDER RESIST COLOR:" at 11488.84,3546.25 h60
  text "X" at 12576.62,3398.87 h60
  text "MATTE" at 12694.62,3398.87 h60
  text "SEMI-GLOSS" at 13312.16,3398.23 h60
  text "IMMERSION GOLD (ENIG)" at 12394.62,3226.1 h60
  text "ENEPIG" at 13732.16,3218.87 h60
  text "SURFACE FINISH:" at 11333.62,3217.87 h60
  text "X" at 12216.62,3217.87 h60
  text "IMM. TIN/SILVER OR EQUIV" at 11663.16,3080.56 h60
  text "OTHER" at 13094.62,3076.62 h60
  text "ARRAY/PANEL:" at 11333.62,2921.24 h60
  text "CUT AND TRIM PER M1 BOARD OUTLINE" at 12394.62,2913.02 h60
  text "N.C. ROUTE" at 12394.62,2777.06 h60
  text "X" at 13082.62,2777.06 h60
  text "V. SCORE" at 13260.62,2777.06 h60
  text "CERTIFICATION:" at 11333.62,2647.93 h60
  text "MATERIALS AND WORKMANSHIP FOR ALL PCBS" at 12058.62,2647.93 h60
  text "TO MEET OR EXCEED THE REQUIREMENTS OF:" at 12058.62,2553.87 h60
  text "X" at 11696.13,2425.24 h60
  text "ANSI IPC-A-600F CLASS ->" at 11824.12,2425.24 h60
  text "X" at 13472.13,2425.24 h60
  text "2" at 13582.12,2425.24 h60
  text "1" at 13267.12,2423.74 h60
  text "3" at 13936.12,2423.74 h60
  text "X" at 12508.13,2277.55 h60
  text "RoHS" at 12636.12,2277.55 h60
  text "OTHER" at 13280.52,2277.55 h60
  text "PER ORDER" at 13677.58,2277.55 h60
  text "ALL BOARDS MUST MEET OR EXCEED UL94-V0 REQUIREMENTS." at 11361.16,2123.72 h60
  text "PCB MUST BEAR THE UL94V-0 UL REGISTERED MATERIAL ID NUMBER" at 11361.16,2007.66 h60
  text "ADDITIONAL REQUIREMENTS:" at 11333.62,1838.24 h60
  text "MICROSECTION:" at 11408.39,1731.11 h60
  text "YES" at 12314.12,1731.11 h60
  text "REQUIRED" at 13175.62,1586.78 h60
  text "BARE BOARD ELEC. TEST:" at 11408.39,1583.92 h60
  text "NONE" at 12714.12,1583.92 h60
  text "X" at 13057.62,1583.92 h60
  text "PER ORDER" at 13767.62,1583.92 h60
  text "XX MIL VIAS REQUIRE NON-CONDUCTIVE FILL AND PLANARIZE" at 11576.53,1378.98 h59
  text "XX MIL VIAS REQUIRE CONDUCTIVE FILL AND PLANARIZE" at 11584.53,1275 h60
  text "OUTER XX MIL TRACES REQUIRE 50 OHM SINGLE-ENDED IMPEDANCE" at 11583.55,1111.61 h58
  text "LAYER 2 & 3 (INNER LAYERS) XX MIL WIDE, XX MIL SPACE / TRACES REQUIRE 100 OHM DIFFERENTIAL IMPEDANCE" at 11575.55,875.9 h60
  text ".Layer_Name" at 577.16,-874.34 h60
M11 Gerber Information:
  lines w10: -291.84,-946.01 6308.16,-946.01 ; -291.84,-742.68 6310.16,-742.68 ; -291.84,-539.34 -291.84,-1149.34 3713.16,-1149.34 6310.16,-1149.34 6310.16,-539.34 -291.34,-539.34 -291.34,-1149.34 1284.16,-1149.34 ; 2173.16,-1149.34 2173.16,-539.34 ; 3440.16,-742.68 3440.16,-539.34 ; 4280.16,-742.68 4280.16,-539.34 ; 4902.16,-1155.84 4902.16,-953.01
  text "ALL ARTWORK VIEWED FROM TOP SIDE" at -228.34,-671.51 h60
  text "BOARD #:" at 2248.16,-671.51 h60
  text ".PRJ_Number" at 2793.66,-671.51 h60
  text "REV:" at 3638.16,-671.51 h60
  text ".PCB_Rev" at 3929.66,-671.51 h60
  text "SVN REV:" at 4476.16,-671.51 h60
  text ".VersionControl_RevNumber" at 4982.16,-671.51 h60
  text "LAYER NAME =" at -228.34,-874.34 h60
  text "TID #:" at 2248.16,-874.84 h60
  text ".TID" at 2793.66,-874.84 h60
  text "PLOT NAME =" at -228.34,-1080.18 h60
  text ".plot_File_Name" at 577.16,-1080.18 h60
  text "GENERATED    :" at 2250.16,-1080.18 h60
  text ".Print_Date" at 3119.66,-1080.18 h60
  text ".Print_Time" at 3848.66,-1080.18 h60
  text "TEXAS INSTRUMENTS" at 5113.16,-1080.18 h60
M12 Stackup:
  drawing of 295 lines, arcs and shapes, not listed
  text "Layer" at 9800.34,7791.67 h60
  text "Name" at 10210.25,7791.67 h60
  text "Material" at 11150,7791.67 h60
  text "Thickness" at 12009.76,7791.67 h60
  text "Constant" at 12659.6,7791.67 h60
  text "Board Layer Stack" at 13229.46,7791.67 h60
  text "Top Overlay" at 10210.25,7671.67 h60
  text "Top Solder" at 10210.25,7551.67 h60
  text "Solder Resist" at 11150,7551.67 h60
  text "0.40mil" at 12009.76,7551.67 h60
  text "3.5" at 12659.6,7551.67 h60
  text "1" at 9800.34,7431.67 h60
  text "Top Layer" at 10210.25,7431.67 h60
  text "2.80mil" at 12009.76,7431.67 h60
  text "Dielectric1" at 10210.25,7311.67 h60
  text "FR-4 High Tg" at 11150,7311.67 h60
  text "5.00mil" at 12009.76,7311.67 h60
  text "4.8" at 12659.6,7311.67 h60
  text "2" at 9800.34,7191.67 h60
  text "Signal Layer 1" at 10210.25,7191.67 h60
  text "2.80mil" at 12009.76,7191.67 h60
  text "Dielectric3" at 10210.25,7071.67 h60
  text "FR-4 High Tg" at 11150,7071.67 h60
  text "40.00mil" at 12009.76,7071.67 h60
  text "4.8" at 12659.6,7071.67 h60
  text "3" at 9800.34,6951.67 h60
  text "Signal Layer 2" at 10210.25,6951.67 h60
  text "2.80mil" at 12009.76,6951.67 h60
  text "Dielectric2" at 10210.25,6831.67 h60
  text "FR-4 High Tg" at 11150,6831.67 h60
  text "5.00mil" at 12009.76,6831.67 h60
  text "4.8" at 12659.6,6831.67 h60
  text "4" at 9800.34,6711.67 h60
  text "Bottom Layer" at 10210.25,6711.67 h60
  text "2.80mil" at 12009.76,6711.67 h60
  text "Bottom Solder" at 10210.25,6591.67 h60
  text "Solder Resist" at 11150,6591.67 h60
  text "0.40mil" at 12009.76,6591.67 h60
  text "3.5" at 12659.6,6591.67 h60
  text "Bottom Overlay" at 10210.25,6471.67 h60
  text ".Layer_Name" at 577.16,-874.34 h60
M13 Component Bodies Top:
  text ".Layer_Name" at 577.16,-874.34 h60
M14 Component Bodies Bottom:
  text ".Layer_Name" at 577.16,-874.34 h60
M15 Courtyards Top:
  text ".Layer_Name" at 577.16,-874.34 h60
M16 Courtyards Bottom:
  text ".Layer_Name" at 577.16,-874.34 h60
Drill Drawing:
  circle w10: c7924.83,5961.36 r27.63
  circle w10: c7924.83,5588.4 r16.58
  circle w10: c7924.83,5588.4 r27.63
  lines w10: 7897.2,5118.75 7952.45,5118.75 7924.83,5063.5 7897.2,5118.75 ; 7897.2,5201.63 7911.01,5201.63 7924.83,5187.82 7938.64,5201.63 7952.45,5201.63 7938.64,5215.44 7952.45,5229.26 7938.64,5229.26 7924.83,5243.07 7911.01,5229.26 7897.2,5229.26 7911.01,5215.44 7897.2,5201.63 ; 7897.2,5312.14 7952.45,5312.14 7952.45,5367.39 7897.2,5367.39 7897.2,5312.14 ; 7897.2,5436.46 7952.45,5436.46 7952.45,5491.71 7897.2,5491.71 7897.2,5436.46 ; 7897.2,5698.91 7911.01,5698.91 7911.01,5685.1 7938.64,5685.1 7938.64,5698.91 7952.45,5698.91 7952.45,5726.54 7938.64,5726.54 7938.64,5740.35 7911.01,5740.35 7911.01,5726.54 7897.2,5726.54 7897.2,5698.91 ; 7897.2,5837.04 7924.83,5809.42 7952.45,5837.04 7924.83,5864.67 7897.2,5837.04 ; 7897.2,6058.06 7924.83,6071.87 7952.45,6058.06 7938.64,6085.68 7952.45,6113.31 7924.83,6099.5 7897.2,6113.31 7911.01,6085.68 7897.2,6058.06 ; 7908.25,5323.19 7941.4,5323.19 7941.4,5356.34 7908.25,5356.34 7908.25,5323.19
  lines w12: 7847.11,5026.2 11078.6,5026.2 ; 7847.11,6145.08 11078.6,6145.08 ; 8184.97,4901.88 8184.97,6269.4 ; 8516.97,4901.88 8516.97,6269.4 ; 9153.54,4901.88 9153.54,6269.4 ; 9412.68,4901.88 9412.68,6269.4 ; 9787.83,4901.88 9787.83,6269.4 ; 10512.17,4901.88 10512.17,6269.4 ; 7847.11,4901.88 11078.6,4901.88 11078.6,6269.4 7847.11,6269.4 7847.11,4901.88
  text "Symbol" at 7921.7,6182.38 h72
  text "Quantity" at 8222.27,6182.38 h72
  text "Finished Hole Size" at 8554.27,6182.38 h72
  text "Plated" at 9190.83,6182.38 h72
  text "Hole Type" at 9449.97,6182.38 h72
  text "Drill Layer Pair" at 9825.13,6182.38 h72
  text "Hole Tolerance" at 10549.46,6182.38 h72
  text "4" at 8222.27,6058.06 h60
  text "159.00mil (4.039mm)" at 8554.27,6058.06 h60
  text "NPTH" at 9190.83,6058.06 h60
  text "Round" at 9449.97,6058.06 h60
  text "Top Layer - Bottom Layer" at 9825.13,6058.06 h60
  text "8" at 8222.27,5933.74 h60
  text "7.87mil (0.200mm)" at 8554.27,5933.74 h60
  text "PTH" at 9190.83,5933.74 h60
  text "Round" at 9449.97,5933.74 h60
  text "Top Layer - Bottom Layer" at 9825.13,5933.74 h60
  text "41" at 8222.27,5809.42 h60
  text "8.00mil (0.203mm)" at 8554.27,5809.42 h60
  text "PTH" at 9190.83,5809.42 h60
  text "Round" at 9449.97,5809.42 h60
  text "Top Layer - Bottom Layer" at 9825.13,5809.42 h60
  text "+/-3.00mil" at 10549.46,5809.42 h60
  text "40" at 8222.27,5685.1 h60
  text "8.00mil (0.203mm)" at 8554.27,5685.1 h60
  text "PTH" at 9190.83,5685.1 h60
  text "Round" at 9449.97,5685.1 h60
  text "Top Layer - Bottom Layer" at 9825.13,5685.1 h60
  text "-3.00mil" at 10549.46,5685.1 h60
  text "5" at 8222.27,5560.78 h60
  text "8.00mil (0.203mm)" at 8554.27,5560.78 h60
  text "PTH" at 9190.83,5560.78 h60
  text "Round" at 9449.97,5560.78 h60
  text "Top Layer - Bottom Layer" at 9825.13,5560.78 h60
  text "+/-3.00mil" at 10549.46,5560.78 h60
  text "316" at 8222.27,5436.46 h60
  text "8.00mil (0.203mm)" at 8554.27,5436.46 h60
  text "PTH" at 9190.83,5436.46 h60
  text "Round" at 9449.97,5436.46 h60
  text "Top Layer - Bottom Layer" at 9825.13,5436.46 h60
  text "9" at 8222.27,5312.14 h60
  text "8.00mil (0.203mm)" at 8554.27,5312.14 h60
  text "PTH" at 9190.83,5312.14 h60
  text "Round" at 9449.97,5312.14 h60
  text "Top Layer - Bottom Layer" at 9825.13,5312.14 h60
  text "25" at 8222.27,5187.82 h60
  text "40.00mil (1.016mm)" at 8554.27,5187.82 h60
  text "PTH" at 9190.83,5187.82 h60
  text "Round" at 9449.97,5187.82 h60
  text "Top Layer - Bottom Layer" at 9825.13,5187.82 h60
  text "4" at 8222.27,5063.5 h60
  text "51.18mil (1.300mm)" at 8554.27,5063.5 h60
  text "PTH" at 9190.83,5063.5 h60
  text "Round" at 9449.97,5063.5 h60
  text "Top Layer - Bottom Layer" at 9825.13,5063.5 h60
  text "452 Total" at 8222.27,4939.18 h60
  text ".Layer_Name" at 577.16,-874.34 h60
M17 Embedded Cavity:
  text ".Layer_Name" at 577.16,-874.34 h60
M18 Embedded Assembly:
  text ".Layer_Name" at 577.16,-874.34 h60
M19 Embedded Keepout:
  text ".Layer_Name" at 577.16,-874.34 h60

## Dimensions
0.16,-415.84 to 1000.16,-415.84 on M2 Board Dimensions
0,0 to 3000,0 on M2 Board Dimensions
0,0 to 0,2500 on M2 Board Dimensions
